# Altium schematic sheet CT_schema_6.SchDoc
size 369 x 245 mm
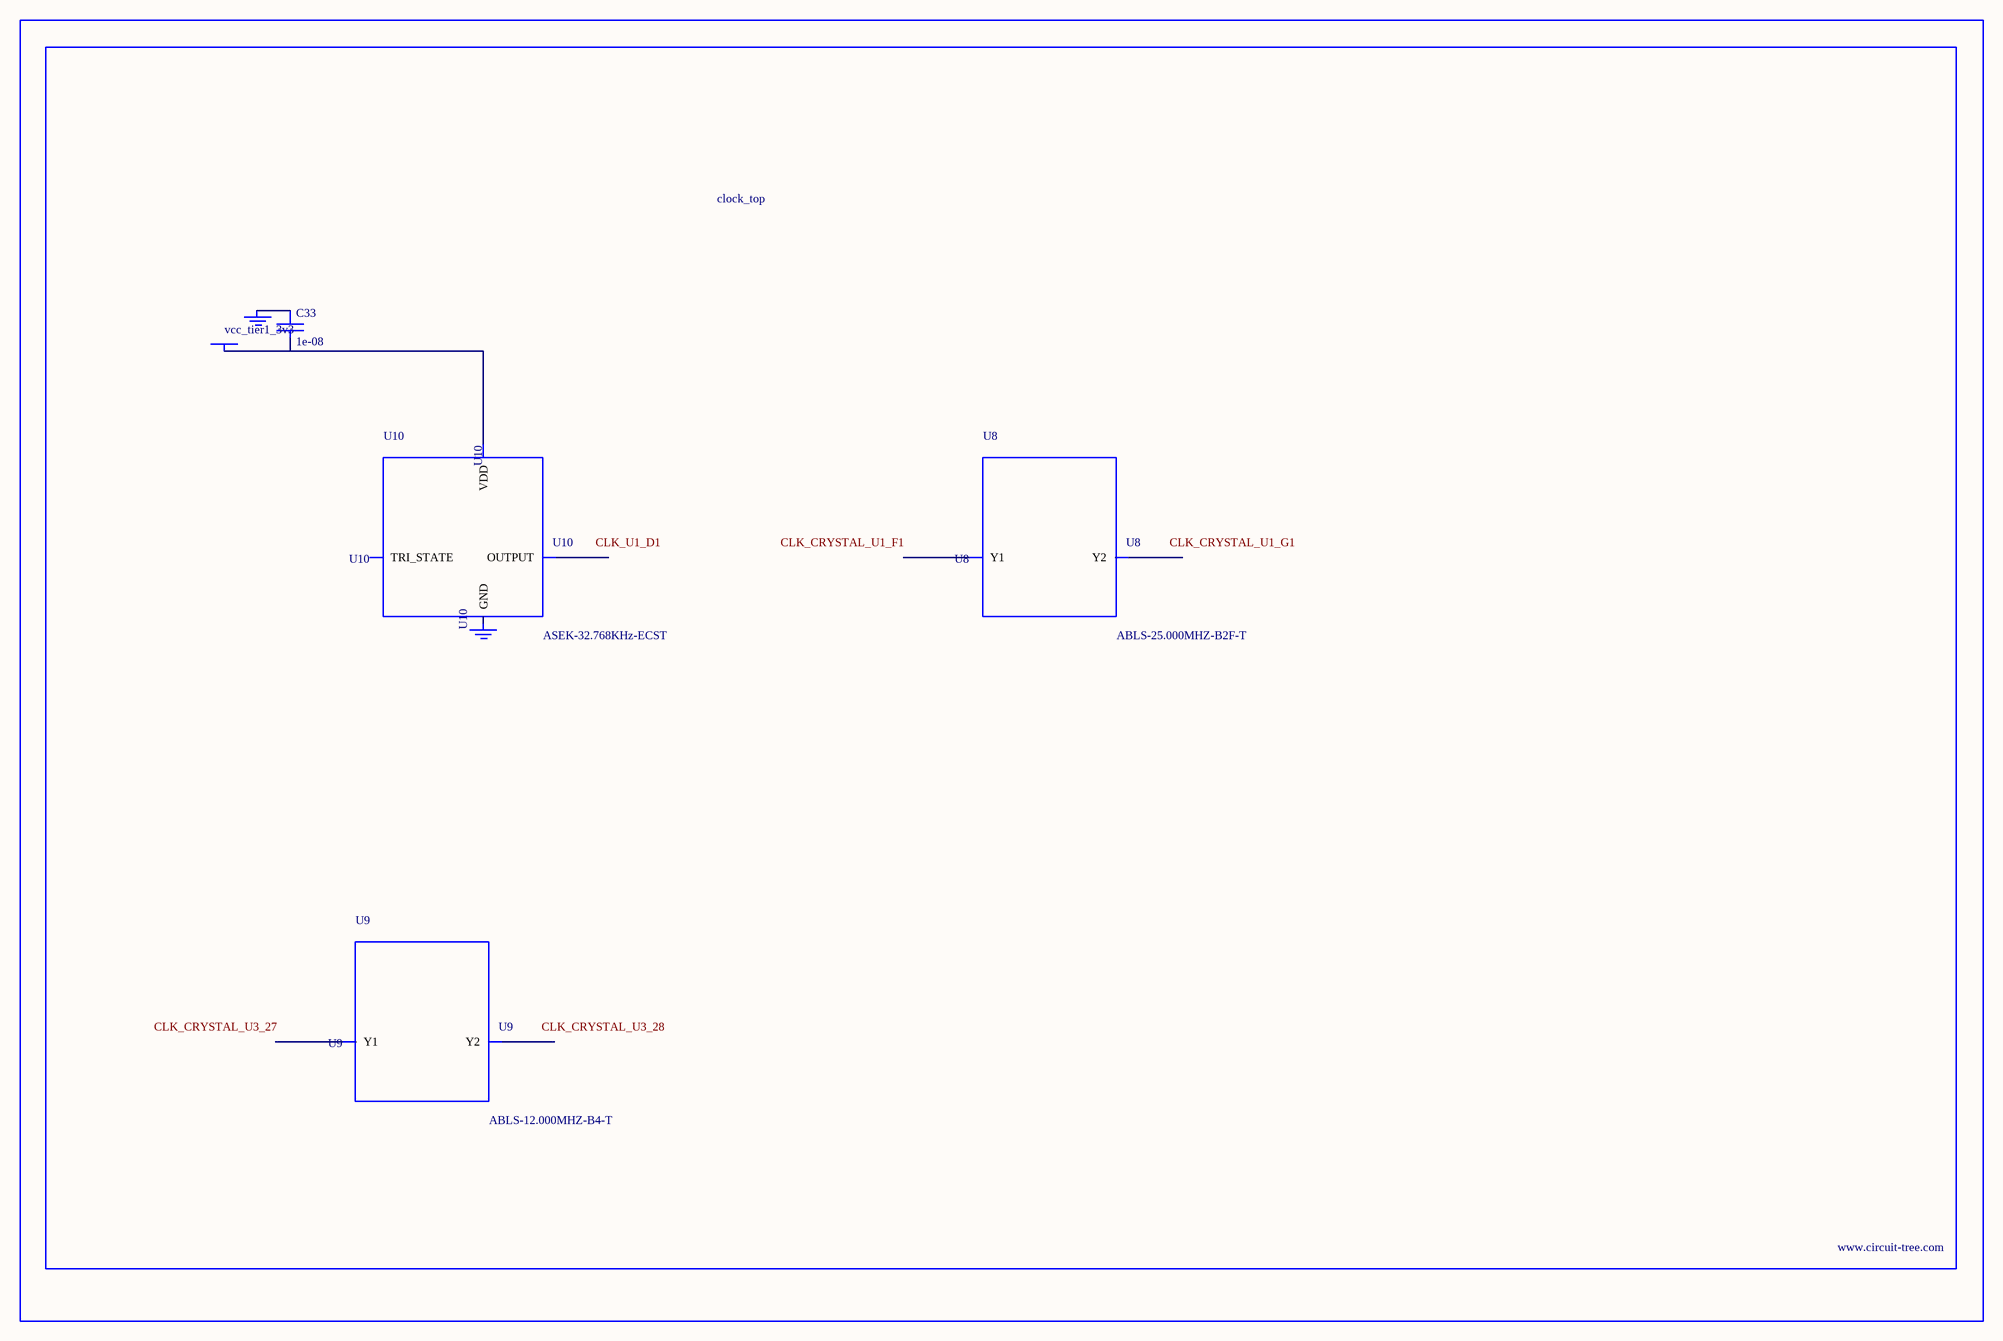
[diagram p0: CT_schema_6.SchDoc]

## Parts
BORDER5  (no value)
C33  1e-08  [C0402]
GND_INSTANCE_5_0  (no value)
GND_INSTANCE_5_1  (no value)
POWER_INSTANCE_5_0  vcc_tier1_3v3
U8  ABLS-25.000MHZ-B2F-T  [ABLS-25.000MHZ-B2F-T]
U9  ABLS-12.000MHZ-B4-T  [ABLS-12.000MHZ-B4-T]
U10  ASEK-32.768KHz-ECST  [ASEK]

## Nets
NetC33_1: C33.1 GND_INSTANCE_5_0.0(GND)
NetC33_2: C33.2 POWER_INSTANCE_5_0.0(PWR) U10.4(VDD)

Not connected (* = marked no-connect by the designer): GND_INSTANCE_5_1 0(GND); U8 1(Y1) 2(Y2); U9 1(Y1) 2(Y2); U10 1(TRI_STATE) 2(GND) 3(OUTPUT)

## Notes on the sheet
- Labels drawn without touching a wire or pin: CLK_CRYSTAL_U1_F1, CLK_CRYSTAL_U1_G1, CLK_CRYSTAL_U3_27, CLK_CRYSTAL_U3_28, CLK_U1_D1

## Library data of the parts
BORDER5 = BORDER_PAGE5
C33 = C0402C103K3RAC
GND_INSTANCE_5_0 GND_INSTANCE_5_1 = GND
POWER_INSTANCE_5_0 = PWR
